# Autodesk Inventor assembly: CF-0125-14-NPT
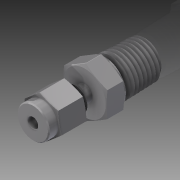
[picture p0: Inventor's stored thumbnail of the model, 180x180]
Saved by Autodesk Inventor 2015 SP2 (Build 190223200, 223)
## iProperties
Created: 2017-11
Part Number: CF-0125-14-NPT
Document SubType Name: Assembly
Designer: JN
Author: JN
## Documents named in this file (5)
- C:\Users\JN\Documents\CAD Drawings\The Sensor Connection\3D\CF\CF-0125-NPT\CF-0125-14-NPT.iam
- C:\Users\JN\Documents\CAD Drawings\The Sensor Connection\3D\CF\CF-0125-NPT\Imported Components\CF-0125-NPT Bottom Ferrule\CF-0125-NPT Bottom Ferrule.ipt
- C:\Users\JN\Documents\CAD Drawings\The Sensor Connection\3D\CF\CF-0125-NPT\Imported Components\CF-0125-NPT Cap\CF-0125-NPT Cap.ipt
- C:\Users\JN\Documents\CAD Drawings\The Sensor Connection\3D\CF\CF-0125-NPT\Imported Components\CF-0125-NPT Top Ferrule\CF-0125-NPT Top Ferrule.ipt
- C:\Users\JN\Documents\CAD Drawings\The Sensor Connection\3D\CF\CF-0125-NPT\Imported Components\CF-0125-14-NPT Threaded Body\CF-0125-14-NPT Threaded Body.ipt
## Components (4 placed, 4 different names)
1. CF-0125-NPT Bottom Ferrule:1 — Mate:4, Mate:5, Mate:9
2. CF-0125-NPT Cap:1 — Mate:6, Mate:7, Mate:8, Rotation:1
3. CF-0125-NPT Top Ferrule:1 — Mate:4, Mate:5, Mate:6, Mate:7
4. CF-0125-14-NPT Threaded Body:1 — Mate:8, Mate:9, Rotation:1
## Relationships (7: Mate 6, RelateRotation 1)
- Mate:4: CF-0125-NPT Bottom Ferrule:1 ↔ CF-0125-NPT Top Ferrule:1
- Mate:5: CF-0125-NPT Bottom Ferrule:1 ↔ CF-0125-NPT Top Ferrule:1
- Mate:6: CF-0125-NPT Cap:1 ↔ CF-0125-NPT Top Ferrule:1
- Mate:7: CF-0125-NPT Cap:1 ↔ CF-0125-NPT Top Ferrule:1
- Mate:8: CF-0125-NPT Cap:1 ↔ CF-0125-14-NPT Threaded Body:1
- Mate:9: CF-0125-NPT Bottom Ferrule:1 ↔ CF-0125-14-NPT Threaded Body:1
- Rotation:1 [RelateRotation]: CF-0125-NPT Cap:1 ↔ CF-0125-14-NPT Threaded Body:1
